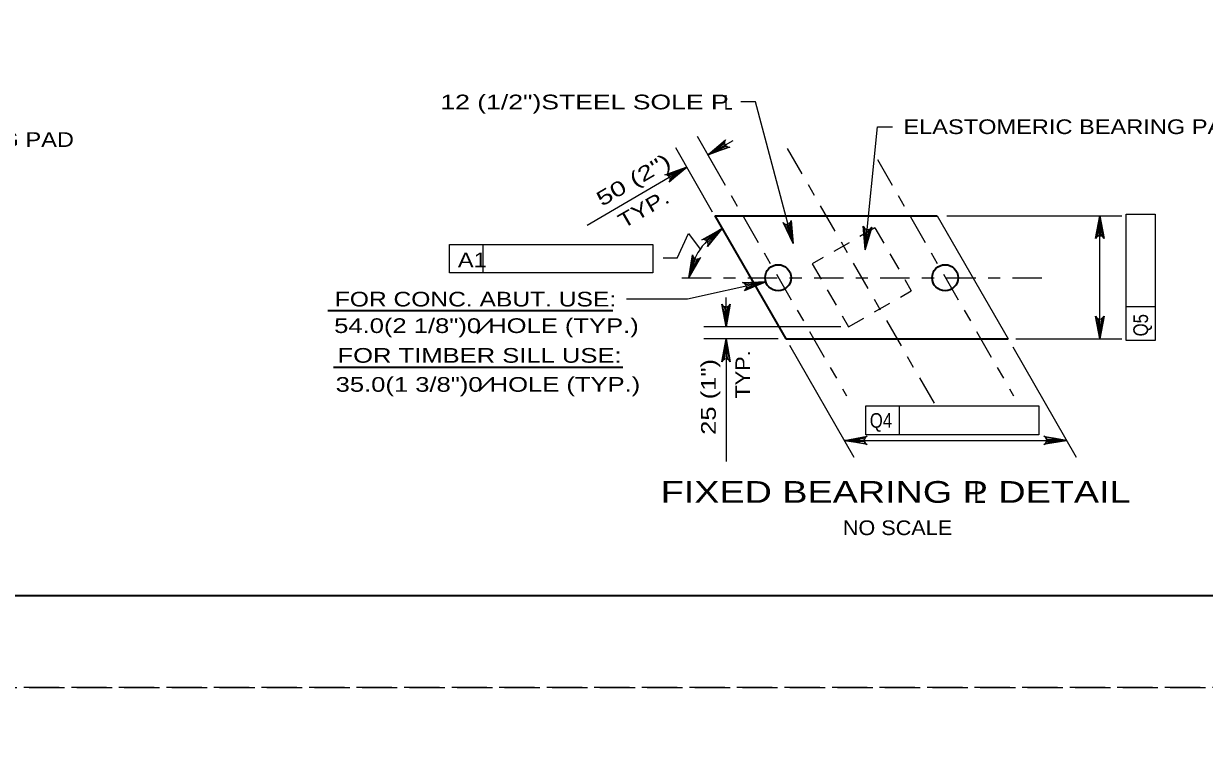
# Model space of a CAD drawing. Extents: x -11 to 79, y -154 to 0.
# Drawn here: x 13.92 to 23.56, y -132.38 to -126.58 of the extents above; entities that cross this region are included whole.
import ezdxf
from ezdxf.enums import TextEntityAlignment as Align

# ---------------------------------------------------------------- set-up
doc = ezdxf.new("R2010")
doc.units = 0
doc.header["$LTSCALE"] = 0.048
for name, pattern in [('DOT_DASHED', [7.7, 5, -1.2, 0.3, -1.2]), ('LONG_DASHED', [7.5, 6, -1.5]), ('MEDIUM_DASHED', [4.5, 3, -1.5])]:
    doc.linetypes.add(name, pattern=pattern)
for name, color, linetype, lineweight in [('1', 7, 'Continuous', 25), ('3', 7, 'Continuous', 25), ('4', 7, 'Continuous', 25), ('63', 7, 'LONG_DASHED', 13)]:
    doc.layers.add(name, color=color, linetype=linetype, lineweight=lineweight)

msp = doc.modelspace()

# ---------------------------------------------------------------- hatches: boundary and pattern name
at = {"layer": '4'}
for points in [[(19.60025, -127.57767), (19.62017, -127.61225), (19.50617, -127.65483)], [(19.22167, -127.79567), (19.24158, -127.83033), (19.33558, -127.75308)], [(22.68575, -128.2705), (22.72575, -128.2705), (22.70575, -128.1505)], [(20.19025, -128.2565), (20.15158, -128.26675), (20.20175, -128.37758)], [(20.823, -128.31142), (20.78325, -128.30742), (20.79108, -128.42883)], [(19.85792, -128.69567), (19.8665, -128.73475), (19.97942, -128.68933)], [(19.63467, -128.93725), (19.67467, -128.93725), (19.65467, -129.05725)], [(22.68575, -129.03567), (22.72575, -129.03567), (22.70575, -129.15567)], [(19.63467, -129.27567), (19.67467, -129.27567), (19.65467, -129.15567)], [(20.74008, -129.96358), (20.74008, -130.00358), (20.62008, -129.98358)], [(22.31433, -129.96358), (22.31433, -130.00358), (22.43433, -129.98358)]]:
    msp.add_hatch(color=256, dxfattribs=at).paths.add_polyline_path(points)

# ---------------------------------------------------------------- linework, layer by layer
at = {"layer": '1', "lineweight": 35}
msp.add_lwpolyline([(1.75, -131.25), (33.25, -131.25), (33.25, -110.75), (1.75, -110.75)], close=True, dxfattribs=at)
at = {"layer": '3', "linetype": 'DOT_DASHED'}
for p, q in [((20.15475, -127.60025), (21.37092, -129.71217)), ((19.52733, -127.69158), (20.63833, -129.62075)), ((20.89025, -127.69158), (22.00125, -129.62075))]:
    msp.add_line(p, q, dxfattribs=at)
at = {"layer": '3', "lineweight": 35}
for p, q in [((19.5645, -128.1505), (21.37875, -128.1505)), ((19.5645, -128.1505), (20.14333, -129.15567)), ((20.14333, -129.15567), (21.95767, -129.15567))]:
    msp.add_line(p, q, dxfattribs=at)
at = {"layer": '3'}
msp.add_line((21.37875, -128.1505), (21.95767, -129.15567), dxfattribs=at)
at = {"layer": '3', "linetype": 'MEDIUM_DASHED'}
for p, q in [((20.8705, -128.24892), (20.35875, -128.54358)), ((20.8705, -128.24892), (21.16633, -128.76258)), ((20.35875, -128.54358), (20.65458, -129.05725)), ((20.65458, -129.05725), (21.16633, -128.76258))]:
    msp.add_line(p, q, dxfattribs=at)
at = {"layer": '3', "lineweight": 35}
for centre in [(20.07993, -128.65627), (21.44287, -128.65627)]:
    msp.add_circle(centre, 0.1063, dxfattribs=at)
at = {"layer": '4'}
for p, q in [((20.79142, -128.42517), (20.89217, -127.42367)), ((20.89217, -127.42367), (21.01217, -127.42367)), ((19.57633, -127.77667), (19.42108, -127.50342)), ((19.50683, -127.65433), (19.71417, -127.53508)), ((19.54392, -128.12183), (19.24575, -127.59708)), ((19.33417, -127.75275), (18.52117, -128.23083)), ((21.45667, -128.1505), (22.88575, -128.1505)), ((22.70575, -129.15567), (22.70575, -128.1505)), ((22.91983, -129.16875), (22.91983, -128.13883)), ((22.91983, -128.13883), (23.15608, -128.13883)), ((23.15608, -128.13883), (23.15608, -129.16875)), ((17.39767, -128.385), (19.05867, -128.385)), ((17.67333, -128.61567), (17.67333, -128.385)), ((19.05867, -128.385), (19.05867, -128.61567)), ((19.256, -128.49533), (19.1425, -128.49533)), ((19.65467, -129.05725), (19.65467, -128.81725)), ((23.15608, -128.89317), (22.91983, -128.89317)), ((20.59208, -129.05725), (19.47467, -129.05725)), ((20.08083, -129.15567), (19.47467, -129.15567)), ((19.65467, -129.15567), (19.65467, -130.15542)), ((20.70092, -130.12392), (20.17492, -129.21058)), ((22.51517, -130.12392), (21.997, -129.224)), ((22.02017, -129.15567), (22.88575, -129.15567)), ((23.15608, -129.16875), (22.91983, -129.16875)), ((20.79542, -129.702), (22.2075, -129.702)), ((20.79542, -129.93825), (20.79542, -129.702)), ((21.071, -129.93825), (21.071, -129.702)), ((22.2075, -129.702), (22.2075, -129.93825)), ((20.62008, -129.98358), (22.43433, -129.98358)), ((22.2075, -129.93825), (20.79542, -129.93825))]:
    msp.add_line(p, q, dxfattribs=at)
at = {"layer": '4', "linetype": 'DOT_DASHED'}
msp.add_line((19.293, -128.65625), (22.23267, -128.65625), dxfattribs=at)
at = {"layer": '4', "lineweight": 35}
for p, q in [((16.40375, -128.92292), (18.73017, -128.92292)), ((17.62458, -129.11033), (17.74417, -128.99075)), ((16.45183, -129.38667), (18.81325, -129.38667)), ((17.63892, -129.57967), (17.74233, -129.47625))]:
    msp.add_line(p, q, dxfattribs=at)
at = {"layer": '4'}
for points in [[(20.20158, -128.37708), (19.89442, -127.22142), (19.77442, -127.22142)], [(19.50683, -127.65433), (19.651, -127.53108), (19.6435, -127.54692), (19.64333, -127.56142), (19.64767, -127.57333), (19.65575, -127.58308), (19.66842, -127.59025), (19.68583, -127.59167), (19.50683, -127.65433), (19.66842, -127.59025), (19.65575, -127.58308), (19.50683, -127.65433), (19.64767, -127.57333), (19.64333, -127.56142), (19.50683, -127.65433), (19.6435, -127.54692)], [(19.33417, -127.75275), (19.19117, -127.87733), (19.1985, -127.8615), (19.19858, -127.847), (19.19408, -127.83508), (19.18592, -127.82542), (19.17317, -127.81842), (19.15575, -127.81708), (19.33417, -127.75275), (19.17317, -127.81842), (19.18592, -127.82542), (19.33417, -127.75275), (19.19408, -127.83508), (19.19858, -127.847), (19.33417, -127.75275), (19.1985, -127.8615)], [(22.70575, -128.1505), (22.74067, -128.33692), (22.73075, -128.32258), (22.71825, -128.31517), (22.70575, -128.313), (22.69325, -128.31517), (22.68075, -128.32258), (22.67083, -128.33692), (22.70575, -128.1505), (22.68075, -128.32258), (22.69325, -128.31517), (22.70575, -128.1505), (22.70575, -128.313), (22.71825, -128.31517), (22.70575, -128.1505), (22.73075, -128.32258)], [(19.62408, -128.25433), (19.50317, -128.40058), (19.50792, -128.38375), (19.50558, -128.36933), (19.49925, -128.35833), (19.48958, -128.35017), (19.47592, -128.34533), (19.4585, -128.34683), (19.62408, -128.25433), (19.47592, -128.34533), (19.48958, -128.35017), (19.62408, -128.25433), (19.49925, -128.35833), (19.50558, -128.36933), (19.62408, -128.25433), (19.50792, -128.38375)], [(20.20158, -128.37708), (20.11992, -128.20592), (20.13325, -128.21725), (20.14725, -128.22117), (20.15983, -128.22), (20.17133, -128.21475), (20.18158, -128.20442), (20.1875, -128.18792), (20.20158, -128.37708), (20.18158, -128.20442), (20.17133, -128.21475), (20.20158, -128.37708), (20.15983, -128.22), (20.14725, -128.22117), (20.20158, -128.37708), (20.13325, -128.21725)], [(20.79142, -128.42517), (20.77533, -128.23617), (20.78375, -128.2515), (20.7955, -128.26008), (20.80767, -128.2635), (20.82033, -128.26258), (20.8335, -128.2565), (20.84483, -128.24317), (20.79142, -128.42517), (20.8335, -128.2565), (20.82033, -128.26258), (20.79142, -128.42517), (20.80767, -128.2635), (20.7955, -128.26008), (20.79142, -128.42517), (20.78375, -128.2515)], [(19.256, -128.49533), (19.34817, -128.29458), (19.44408, -128.42292)], [(19.05867, -128.61567), (17.39767, -128.61567), (17.39767, -128.385)], [(19.35075, -128.65608), (19.38092, -128.46883), (19.38542, -128.48575), (19.39467, -128.49692), (19.40575, -128.50325), (19.41825, -128.50542), (19.4325, -128.50267), (19.44667, -128.4925), (19.35075, -128.65608), (19.4325, -128.50267), (19.41825, -128.50542), (19.35075, -128.65608), (19.40575, -128.50325), (19.39467, -128.49692), (19.35075, -128.65608), (19.38542, -128.48575)], [(19.979, -128.68942), (19.34083, -128.83), (18.84375, -128.83)], [(19.979, -128.68942), (19.8045, -128.76367), (19.81633, -128.75083), (19.82092, -128.73708), (19.82033, -128.72442), (19.8155, -128.71267), (19.80558, -128.702), (19.78942, -128.69542), (19.979, -128.68942), (19.80558, -128.702), (19.8155, -128.71267), (19.979, -128.68942), (19.82033, -128.72442), (19.82092, -128.73708), (19.979, -128.68942), (19.81633, -128.75083)], [(19.65467, -129.05725), (19.61975, -128.87083), (19.62967, -128.88517), (19.64217, -128.89258), (19.65467, -128.89475), (19.66717, -128.89258), (19.67967, -128.88517), (19.68958, -128.87083), (19.65467, -129.05725), (19.67967, -128.88517), (19.66717, -128.89258), (19.65467, -129.05725), (19.65467, -128.89475), (19.64217, -128.89258), (19.65467, -129.05725), (19.62967, -128.88517)], [(22.70575, -129.15567), (22.67083, -128.96925), (22.68075, -128.98358), (22.69325, -128.991), (22.70575, -128.99317), (22.71825, -128.991), (22.73075, -128.98358), (22.74067, -128.96925), (22.70575, -129.15567), (22.73075, -128.98358), (22.71825, -128.991), (22.70575, -129.15567), (22.70575, -128.99317), (22.69325, -128.991), (22.70575, -129.15567), (22.68075, -128.98358)], [(19.65467, -129.15567), (19.68958, -129.34208), (19.67967, -129.32775), (19.66717, -129.32033), (19.65467, -129.31817), (19.64217, -129.32033), (19.62967, -129.32775), (19.61975, -129.34208), (19.65467, -129.15567), (19.62967, -129.32775), (19.64217, -129.32033), (19.65467, -129.15567), (19.65467, -129.31817), (19.66717, -129.32033), (19.65467, -129.15567), (19.67967, -129.32775)], [(20.62008, -129.98358), (20.8065, -129.94867), (20.79217, -129.95858), (20.78475, -129.97108), (20.78258, -129.98358), (20.78475, -129.99608), (20.79217, -130.00858), (20.8065, -130.0185), (20.62008, -129.98358), (20.79217, -130.00858), (20.78475, -129.99608), (20.62008, -129.98358), (20.78258, -129.98358), (20.78475, -129.97108), (20.62008, -129.98358), (20.79217, -129.95858)], [(22.43433, -129.98358), (22.24792, -130.0185), (22.26225, -130.00858), (22.26967, -129.99608), (22.27183, -129.98358), (22.26967, -129.97108), (22.26225, -129.95858), (22.24792, -129.94867), (22.43433, -129.98358), (22.26225, -129.95858), (22.26967, -129.97108), (22.43433, -129.98358), (22.27183, -129.98358), (22.26967, -129.99608), (22.43433, -129.98358), (22.26225, -130.00858)]]:
    msp.add_lwpolyline(points, dxfattribs=at)
for points in [[(19.60025, -127.57767), (19.62017, -127.61225), (19.50617, -127.65483)], [(19.22167, -127.79567), (19.24158, -127.83033), (19.33558, -127.75308)], [(22.68575, -128.2705), (22.72575, -128.2705), (22.70575, -128.1505)], [(20.19025, -128.2565), (20.15158, -128.26675), (20.20175, -128.37758)], [(20.823, -128.31142), (20.78325, -128.30742), (20.79108, -128.42883)], [(19.85792, -128.69567), (19.8665, -128.73475), (19.97942, -128.68933)], [(19.63467, -128.93725), (19.67467, -128.93725), (19.65467, -129.05725)], [(22.68575, -129.03567), (22.72575, -129.03567), (22.70575, -129.15567)], [(19.63467, -129.27567), (19.67467, -129.27567), (19.65467, -129.15567)], [(20.74008, -129.96358), (20.74008, -130.00358), (20.62008, -129.98358)], [(22.31433, -129.96358), (22.31433, -130.00358), (22.43433, -129.98358)]]:
    msp.add_lwpolyline(points, close=True, dxfattribs=at)
msp.add_arc((19.90467, -128.74128), 0.5599, 119.93576, 171.2608, dxfattribs=at)
at = {"layer": '63'}
for points in [[(0, -132), (34, -132), (34, -110), (0, -110)], [(0, -154), (34, -154), (34, -132), (0, -132)]]:
    msp.add_lwpolyline(points, close=True, dxfattribs=at)

# ---------------------------------------------------------------- texts
at = {"layer": '4'}
for s, width, p in [('12 (1/2")STEEL SOLE P', 1.35, (17.32375, -127.28192)), ('L', 0.75, (19.63967, -127.28358)), ('ELASTOMERIC BEARING PAD', 1.2, (21.10217, -127.48375)), ('ELASTOMERIC BEARING PAD', 1.2, (11.58317, -127.58867)), ('FOR CONC. ABUT. USE:', 1.25, (16.46208, -128.89092)), ('54.0(2 1/8")0 HOLE (TYP.)', 1.3, (16.45683, -129.10742)), ('FOR TIMBER SILL USE:', 1.3, (16.48425, -129.35008)), ('35.0(1 3/8")0 HOLE (TYP.)', 1.3, (16.46892, -129.58708)), ('NO SCALE', 1.1, (20.60783, -130.75683))]:
    msp.add_text(s, height=0.12, dxfattribs=dict(at, width=width)).set_placement(p)
for s, rotation, width, p in [('50 (2")', 30.466, 1.4, (18.92916, -127.90889)), ('TYP.', 29.936, 1.25, (19.01143, -128.1465)), ('Q5', 90, 0.85, (23.09892, -129.04387)), ('TYP.', 90, 1.1, (19.85183, -129.44521)), ('25 (1")', 90, 1.3, (19.57158, -129.62904))]:
    msp.add_text(s, height=0.12, rotation=rotation, dxfattribs=dict(at, width=width)).set_placement(p, align=Align.CENTER)
for s, height, width, p in [('A1', 0.12, 1.2, (17.58413, -128.57175)), ('Q4', 0.12, 0.85, (20.91912, -129.88108)), ('FIXED BEARING P DETAIL', 0.1772, 1.3, (21.03879, -130.49308)), ('L', 0.1772, 0.75, (21.7245, -130.4945))]:
    msp.add_text(s, height=height, dxfattribs=dict(at, width=width)).set_placement(p, align=Align.CENTER)

doc.saveas('drawing.dxf')
